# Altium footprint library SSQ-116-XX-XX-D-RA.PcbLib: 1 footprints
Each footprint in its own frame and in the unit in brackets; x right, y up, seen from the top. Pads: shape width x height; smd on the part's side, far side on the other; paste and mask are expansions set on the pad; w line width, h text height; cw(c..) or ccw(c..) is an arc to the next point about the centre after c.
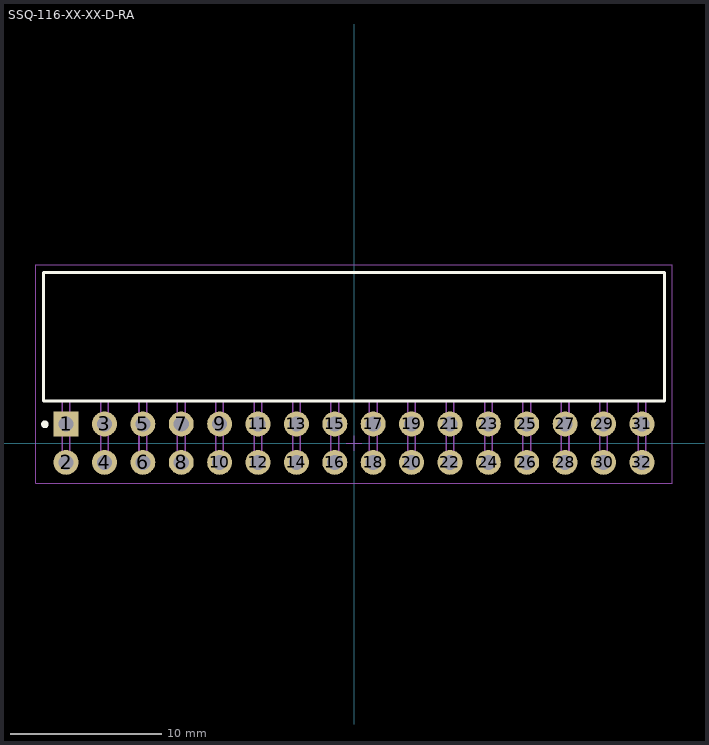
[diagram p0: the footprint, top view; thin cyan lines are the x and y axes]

## SSQ-116-XX-XX-D-RA [mm] "2.54mm pitch, 32 pin, socket strip; r/a, double row, PTH"
height 8.51
pads (32):
  rect 1.65x1.65 / inner round 1.65 / far side rect 1.65x1.65 hole 1 mask+0: 1(-19.05,1.27)
  round 1.65 hole 1 mask+0: 2(-19.05,-1.27) 3(-16.51,1.27) 4(-16.51,-1.27) 5(-13.97,1.27) 6(-13.97,-1.27) 7(-11.43,1.27) 8(-11.43,-1.27) 9(-8.89,1.27) 10(-8.89,-1.27) 11(-6.35,1.27) 12(-6.35,-1.27) 13(-3.81,1.27) 14(-3.81,-1.27) 15(-1.27,1.27) 16(-1.27,-1.27) 17(1.27,1.27) 18(1.27,-1.27) 19(3.81,1.27) 20(3.81,-1.27) 21(6.35,1.27) 22(6.35,-1.27) 23(8.89,1.27) 24(8.89,-1.27) 25(11.43,1.27) 26(11.43,-1.27) 27(13.97,1.27) 28(13.97,-1.27) 29(16.51,1.27) 30(16.51,-1.27) 31(19.05,1.27) 32(19.05,-1.27)
Top Overlay:
  circle w0.25: c-20.45,1.25 r0.125
  lines w0.2: -20.55,2.8 20.55,2.8 20.55,11.3 -20.55,11.3 -20.55,2.8
Mechanical 12:
  lines w0.001: -20.55,2.8 20.55,2.8 20.55,11.3 -20.55,11.3 -20.55,2.8
Mechanical 13:
  lines w0.1: -19.304,2.794 -19.304,-1.27 ccw(c-19.05,-1.27) -18.796,-1.27 -18.796,2.794 ; -16.764,2.794 -16.764,-1.27 ccw(c-16.51,-1.27) -16.256,-1.27 -16.256,2.794 ; -14.224,2.794 -14.224,-1.27 ccw(c-13.97,-1.27) -13.716,-1.27 -13.716,2.794 ; -11.684,2.794 -11.684,-1.27 ccw(c-11.43,-1.27) -11.176,-1.27 -11.176,2.794 ; -9.144,2.794 -9.144,-1.27 ccw(c-8.89,-1.27) -8.636,-1.27 -8.636,2.794 ; -6.604,2.794 -6.604,-1.27 ccw(c-6.35,-1.27) -6.096,-1.27 -6.096,2.794 ; -4.064,2.794 -4.064,-1.27 ccw(c-3.81,-1.27) -3.556,-1.27 -3.556,2.794 ; -1.524,2.794 -1.524,-1.27 ccw(c-1.27,-1.27) -1.016,-1.27 -1.016,2.794 ; 1.016,2.794 1.016,-1.27 ccw(c1.27,-1.27) 1.524,-1.27 1.524,2.794 ; 3.556,2.794 3.556,-1.27 ccw(c3.81,-1.27) 4.064,-1.27 4.064,2.794 ; 6.096,2.794 6.096,-1.27 ccw(c6.35,-1.27) 6.604,-1.27 6.604,2.794 ; 8.636,2.794 8.636,-1.27 ccw(c8.89,-1.27) 9.144,-1.27 9.144,2.794 ; 11.176,2.794 11.176,-1.27 ccw(c11.43,-1.27) 11.684,-1.27 11.684,2.794 ; 13.716,2.794 13.716,-1.27 ccw(c13.97,-1.27) 14.224,-1.27 14.224,2.794 ; 16.256,2.794 16.256,-1.27 ccw(c16.51,-1.27) 16.764,-1.27 16.764,2.794 ; 18.796,2.794 18.796,-1.27 ccw(c19.05,-1.27) 19.304,-1.27 19.304,2.794 ; -20.55,2.8 20.55,2.8 20.55,11.3 -20.55,11.3 -20.55,2.8
  text ".Designator" at 0.127,-0.127 h1.52
Mechanical 15:
  lines w0.05: -0.5,0 0.5,0 ; 0,-0.5 0,0.5 ; -21.05,-2.65 21.05,-2.65 21.05,11.8 -21.05,11.8 -21.05,-2.65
